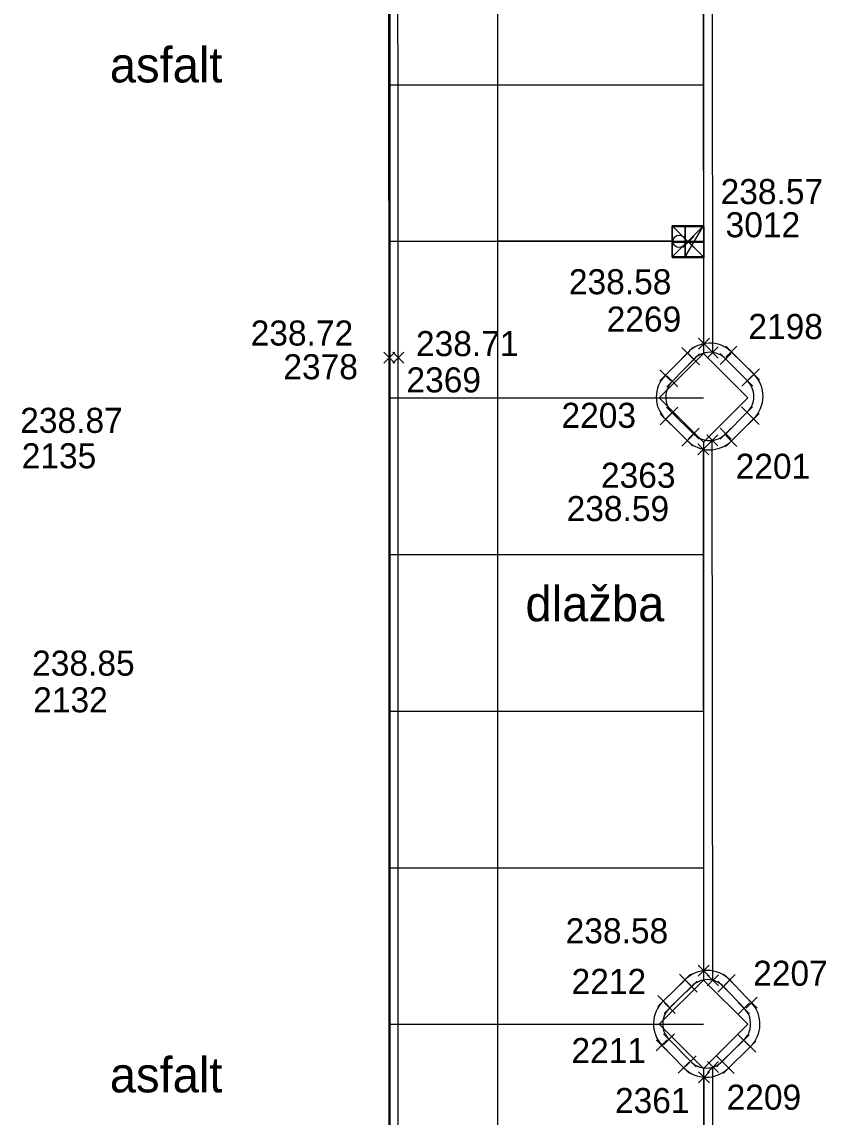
# Model space of a CAD drawing. Extents: x -264222 to -263676, y -1242344 to -1242060.
# Drawn here: x -264131.44 to -264118.61, y -1242231.96 to -1242214.48 of the extents above; entities that cross this region are included whole.
import ezdxf

# ---------------------------------------------------------------- set-up
doc = ezdxf.new("R2010")
doc.units = 0
for name, color, linetype in [('BODY_CISLO', 7, 'Continuous'), ('BODY_SYMBOL', 7, 'Continuous'), ('BODY_VYSKA', 7, 'Continuous'), ('BODY_VYSKY_UV', 7, 'Continuous'), ('KOORDINACNA_SITUACIA_DSP', 7, 'Continuous'), ('POPIS', 7, 'Continuous'), ('PROJEKT_DRS_OBRUBNIKY_KOMUNIKACIE', 7, 'Continuous'), ('PROJEKT_DRS_TDZ_VODOROVNE', 7, 'Continuous'), ('PROJEKT_DRS_UV_STAVBY', 7, 'Continuous'), ('SO_20-3_OBRUBNIKY_DOLNA_HRANA', 7, 'Continuous'), ('SO_20-3_OBRUBNIKY_HORNA_HRANA', 7, 'Continuous'), ('ULICNA_VPUST_POKLOP', 7, 'Continuous')]:
    doc.layers.add(name, color=color, linetype=linetype)

msp = doc.modelspace()

# ---------------------------------------------------------------- linework, layer by layer
at = {"layer": 'BODY_SYMBOL'}
for p, q in [((-264120.901, -1242218.083), (-264120.725, -1242217.907)), ((-264120.725, -1242218.083), (-264120.901, -1242217.907)), ((-264120.649, -1242219.705), (-264120.473, -1242219.529)), ((-264120.473, -1242219.705), (-264120.649, -1242219.529)), ((-264120.914, -1242219.853), (-264120.738, -1242219.677)), ((-264120.738, -1242219.853), (-264120.914, -1242219.677)), ((-264120.51, -1242219.845), (-264120.334, -1242219.669)), ((-264120.334, -1242219.845), (-264120.51, -1242219.669)), ((-264120.214, -1242219.833), (-264120.038, -1242219.657)), ((-264120.038, -1242219.833), (-264120.214, -1242219.657)), ((-264125.672, -1242219.928), (-264125.496, -1242219.752)), ((-264125.496, -1242219.928), (-264125.672, -1242219.752)), ((-264125.528, -1242219.929), (-264125.352, -1242219.753)), ((-264125.352, -1242219.929), (-264125.528, -1242219.753)), ((-264120.81, -1242219.952), (-264120.634, -1242219.776)), ((-264120.634, -1242219.952), (-264120.81, -1242219.776)), ((-264120.304, -1242219.948), (-264120.128, -1242219.772)), ((-264120.128, -1242219.948), (-264120.304, -1242219.772)), ((-264121.264, -1242220.207), (-264121.088, -1242220.031)), ((-264121.088, -1242220.207), (-264121.264, -1242220.031)), ((-264119.851, -1242220.193), (-264119.675, -1242220.017)), ((-264119.675, -1242220.193), (-264119.851, -1242220.017)), ((-264121.152, -1242220.303), (-264120.976, -1242220.127)), ((-264120.976, -1242220.303), (-264121.152, -1242220.127)), ((-264119.957, -1242220.297), (-264119.781, -1242220.121)), ((-264119.781, -1242220.297), (-264119.957, -1242220.121)), ((-264121.26, -1242220.911), (-264121.084, -1242220.735)), ((-264121.084, -1242220.911), (-264121.26, -1242220.735)), ((-264121.157, -1242220.806), (-264120.981, -1242220.63)), ((-264120.981, -1242220.806), (-264121.157, -1242220.63)), ((-264119.963, -1242220.801), (-264119.787, -1242220.625)), ((-264119.787, -1242220.801), (-264119.963, -1242220.625)), ((-264119.857, -1242220.905), (-264119.681, -1242220.729)), ((-264119.681, -1242220.905), (-264119.857, -1242220.729)), ((-264120.914, -1242221.253), (-264120.738, -1242221.077)), ((-264120.738, -1242221.253), (-264120.914, -1242221.077)), ((-264120.814, -1242221.143), (-264120.638, -1242220.967)), ((-264120.638, -1242221.143), (-264120.814, -1242220.967)), ((-264120.517, -1242221.248), (-264120.341, -1242221.072)), ((-264120.341, -1242221.248), (-264120.517, -1242221.072)), ((-264120.301, -1242221.142), (-264120.125, -1242220.966)), ((-264120.125, -1242221.142), (-264120.301, -1242220.966)), ((-264120.212, -1242221.257), (-264120.036, -1242221.081)), ((-264120.036, -1242221.257), (-264120.212, -1242221.081)), ((-264120.659, -1242221.389), (-264120.483, -1242221.213)), ((-264120.483, -1242221.389), (-264120.659, -1242221.213)), ((-264120.952, -1242229.86), (-264120.776, -1242229.684)), ((-264120.776, -1242229.86), (-264120.952, -1242229.684)), ((-264120.653, -1242229.713), (-264120.477, -1242229.537)), ((-264120.477, -1242229.713), (-264120.653, -1242229.537)), ((-264120.508, -1242229.867), (-264120.332, -1242229.691)), ((-264120.332, -1242229.867), (-264120.508, -1242229.691)), ((-264120.238, -1242229.862), (-264120.062, -1242229.686)), ((-264120.062, -1242229.862), (-264120.238, -1242229.686)), ((-264120.848, -1242229.967), (-264120.672, -1242229.791)), ((-264120.672, -1242229.967), (-264120.848, -1242229.791)), ((-264120.34, -1242229.967), (-264120.164, -1242229.791)), ((-264120.164, -1242229.967), (-264120.34, -1242229.791)), ((-264121.297, -1242230.198), (-264121.121, -1242230.022)), ((-264121.121, -1242230.198), (-264121.297, -1242230.022)), ((-264121.197, -1242230.308), (-264121.021, -1242230.132)), ((-264121.021, -1242230.308), (-264121.197, -1242230.132)), ((-264120.009, -1242230.313), (-264119.833, -1242230.137)), ((-264119.833, -1242230.313), (-264120.009, -1242230.137)), ((-264119.89, -1242230.227), (-264119.714, -1242230.051)), ((-264119.714, -1242230.227), (-264119.89, -1242230.051)), ((-264121.322, -1242230.905), (-264121.146, -1242230.729)), ((-264121.146, -1242230.905), (-264121.322, -1242230.729)), ((-264121.207, -1242230.811), (-264121.031, -1242230.635)), ((-264121.031, -1242230.811), (-264121.207, -1242230.635)), ((-264120.018, -1242230.826), (-264119.842, -1242230.65)), ((-264119.842, -1242230.826), (-264120.018, -1242230.65)), ((-264119.911, -1242230.929), (-264119.735, -1242230.753)), ((-264119.735, -1242230.929), (-264119.911, -1242230.753)), ((-264120.971, -1242231.265), (-264120.795, -1242231.089)), ((-264120.795, -1242231.265), (-264120.971, -1242231.089)), ((-264120.864, -1242231.161), (-264120.688, -1242230.985)), ((-264120.688, -1242231.161), (-264120.864, -1242230.985)), ((-264120.506, -1242231.253), (-264120.33, -1242231.077)), ((-264120.33, -1242231.253), (-264120.506, -1242231.077)), ((-264120.36, -1242231.163), (-264120.184, -1242230.987)), ((-264120.184, -1242231.163), (-264120.36, -1242230.987)), ((-264120.257, -1242231.27), (-264120.081, -1242231.094)), ((-264120.081, -1242231.27), (-264120.257, -1242231.094)), ((-264120.648, -1242231.415), (-264120.472, -1242231.239)), ((-264120.472, -1242231.415), (-264120.648, -1242231.239))]:
    msp.add_line(p, q, dxfattribs=at)
at = {"layer": 'KOORDINACNA_SITUACIA_DSP'}
for p, q in [((-264123.854, -1242207), (-264123.854, -1242236.976)), ((-264120.568, -1242211.189), (-264120.568, -1242219.774)), ((-264120.86, -1242218.232), (-264120.86, -1242217.732)), ((-264120.86, -1242217.732), (-264120.57, -1242217.732)), ((-264120.86, -1242218.232), (-264120.57, -1242217.732)), ((-264120.86, -1242218.232), (-264120.57, -1242217.732)), ((-264120.57, -1242217.732), (-264120.86, -1242217.732)), ((-264120.86, -1242217.732), (-264120.86, -1242218.232)), ((-264120.57, -1242217.732), (-264120.57, -1242218.232)), ((-264121.058, -1242217.982), (-264123.854, -1242217.982)), ((-264120.57, -1242218.232), (-264120.86, -1242218.232)), ((-264120.568, -1242221.189), (-264120.568, -1242229.774)), ((-264120.568, -1242231.189), (-264120.568, -1242239.774))]:
    msp.add_line(p, q, dxfattribs=at)
for points in [[(-264120.568, -1242219.775), (-264119.861, -1242220.482), (-264120.568, -1242221.189), (-264121.275, -1242220.482)], [(-264120.568, -1242229.775), (-264119.861, -1242230.482), (-264120.568, -1242231.189), (-264121.275, -1242230.482)]]:
    msp.add_lwpolyline(points, close=True, dxfattribs=at)
msp.add_circle((-264120.958, -1242217.982), 0.1, dxfattribs=at)
at = {"layer": 'PROJEKT_DRS_OBRUBNIKY_KOMUNIKACIE'}
for p, q in [((-264125.568, -1242270.982), (-264125.568, -1242191.482)), ((-264120.568, -1242211.189), (-264120.568, -1242219.774)), ((-264120.568, -1242221.189), (-264120.568, -1242229.774)), ((-264120.568, -1242231.189), (-264120.568, -1242239.774))]:
    msp.add_line(p, q, dxfattribs=at)
for points in [[(-264120.568, -1242219.775), (-264119.861, -1242220.482), (-264120.568, -1242221.189), (-264121.275, -1242220.482), (-264120.568, -1242219.775)], [(-264120.568, -1242229.775), (-264119.861, -1242230.482), (-264120.568, -1242231.189), (-264121.275, -1242230.482), (-264120.568, -1242229.775)]]:
    msp.add_lwpolyline(points, dxfattribs=at)
at = {"layer": 'PROJEKT_DRS_TDZ_VODOROVNE'}
for p, q in [((-264125.568, -1242215.482), (-264120.568, -1242215.482)), ((-264125.568, -1242217.982), (-264120.568, -1242217.982)), ((-264125.568, -1242220.482), (-264120.568, -1242220.482)), ((-264125.568, -1242222.982), (-264120.568, -1242222.982)), ((-264125.568, -1242225.482), (-264120.568, -1242225.482)), ((-264125.568, -1242227.982), (-264120.568, -1242227.982)), ((-264125.568, -1242230.482), (-264120.568, -1242230.482))]:
    msp.add_line(p, q, dxfattribs=at)
at = {"layer": 'PROJEKT_DRS_UV_STAVBY'}
msp.add_lwpolyline([(-264121.07, -1242218.232), (-264121.07, -1242217.732), (-264120.57, -1242217.732), (-264120.57, -1242218.232), (-264121.07, -1242218.232), (-264120.57, -1242217.732), (-264121.07, -1242217.732), (-264120.57, -1242218.232)], dxfattribs=at)
at = {"layer": 'SO_20-3_OBRUBNIKY_DOLNA_HRANA'}
for p, q in [((-264120.561, -1242219.617), (-264120.573, -1242211.348)), ((-264120.826, -1242219.765), (-264121.176, -1242220.119)), ((-264120.126, -1242219.745), (-264119.763, -1242220.105)), ((-264120.826, -1242221.165), (-264121.172, -1242220.823)), ((-264119.769, -1242220.817), (-264120.124, -1242221.169)), ((-264120.565, -1242229.625), (-264120.571, -1242221.301)), ((-264121.209, -1242230.11), (-264120.864, -1242229.772)), ((-264120.15, -1242229.774), (-264119.802, -1242230.139)), ((-264120.883, -1242231.177), (-264121.234, -1242230.817)), ((-264119.823, -1242230.841), (-264120.169, -1242231.182)), ((-264120.554, -1242239.646), (-264120.56, -1242231.327))]:
    msp.add_line(p, q, dxfattribs=at)
for points in [[(-264125.573, -1242270.915), (-264125.578, -1242264.895), (-264125.575, -1242255.299), (-264125.581, -1242244.324), (-264125.582, -1242233.844), (-264125.584, -1242219.84), (-264125.593, -1242209.81), (-264125.59, -1242197.798), (-264125.59, -1242191.484)], [(-264125.429, -1242270.662), (-264125.437, -1242264.9), (-264125.431, -1242255.315), (-264125.435, -1242244.34), (-264125.439, -1242233.845), (-264125.44, -1242219.841), (-264125.448, -1242209.814), (-264125.447, -1242197.797), (-264125.435, -1242191.484)]]:
    msp.add_lwpolyline(points, dxfattribs=at)
for centre, major_axis, ratio, start_param, end_param in [((-264120.466, -1242220.098), (-0.488, 0.046), 0.999933, 4.040271, 5.631388), ((-264120.832, -1242220.469), (0.216, -0.441), 0.999979, 3.462744, 5.062042), ((-264120.123, -1242220.458), (0.183, 0.47), 0.998877, 4.292351, 5.859751), ((-264120.473, -1242220.812), (0.444, 0.228), 0.999924, 3.453691, 5.012696), ((-264120.508, -1242230.12), (-0.447, -0.218), 0.99998, 3.456563, 5.056606), ((-264120.863, -1242230.476), (0.378, -0.333), 0.999798, 3.050143, 4.60564), ((-264120.165, -1242230.48), (0.194, 0.458), 0.999375, 4.300208, 5.866467), ((-264120.524, -1242230.826), (0.502, -0.004), 0.999977, 3.921399, 5.503379)]:
    msp.add_ellipse(centre, major_axis=major_axis, ratio=ratio, start_param=start_param, end_param=end_param, dxfattribs=at)
at = {"layer": 'SO_20-3_OBRUBNIKY_HORNA_HRANA'}
for p, q in [((-264120.422, -1242219.757), (-264120.426, -1242211.199)), ((-264121.064, -1242220.215), (-264120.722, -1242219.864)), ((-264120.216, -1242219.86), (-264119.869, -1242220.209)), ((-264120.726, -1242221.055), (-264121.069, -1242220.718)), ((-264119.875, -1242220.713), (-264120.213, -1242221.054)), ((-264120.42, -1242229.779), (-264120.429, -1242221.16)), ((-264121.109, -1242230.22), (-264120.76, -1242229.879)), ((-264120.252, -1242229.879), (-264119.921, -1242230.225)), ((-264120.776, -1242231.073), (-264121.119, -1242230.723)), ((-264119.93, -1242230.738), (-264120.272, -1242231.075)), ((-264120.414, -1242239.803), (-264120.418, -1242231.165))]:
    msp.add_line(p, q, dxfattribs=at)
for centre, major_axis, ratio, start_param, end_param in [((-264120.467, -1242220.104), (-0.348, -0.038), 0.999249, 3.8025, 5.417886), ((-264120.818, -1242220.469), (-0.004, -0.354), 0.998351, 3.922572, 5.502206), ((-264120.115, -1242220.458), (0.08, 0.341), 0.999323, 4.126273, 5.733445), ((-264120.47, -1242220.803), (0.356, 0.05), 0.998417, 3.778494, 5.368139), ((-264120.506, -1242230.114), (-0.342, -0.05), 0.999153, 3.74362, 5.393103), ((-264120.865, -1242230.477), (0.068, -0.348), 0.997854, 3.70915, 5.287368), ((-264120.171, -1242230.477), (0.16, 0.317), 0.998795, 4.356433, 5.972219), ((-264120.523, -1242230.834), (0.348, -0.001), 0.998886, 3.904066, 5.520712)]:
    msp.add_ellipse(centre, major_axis=major_axis, ratio=ratio, start_param=start_param, end_param=end_param, dxfattribs=at)
at = {"layer": 'ULICNA_VPUST_POKLOP'}
msp.add_line((-264120.813, -1242217.995), (-264120.813, -1242217.995), dxfattribs=at)
msp.add_lwpolyline([(-264121.063, -1242217.995), (-264121.063, -1242217.745), (-264120.563, -1242217.745), (-264120.563, -1242218.245), (-264121.063, -1242218.245), (-264121.063, -1242217.995), (-264120.563, -1242217.995)], dxfattribs=at)

# ---------------------------------------------------------------- texts
at = {"layer": 'BODY_CISLO'}
for s, p in [('3012', (-264120.216, -1242217.917)), ('2269', (-264122.114, -1242219.423)), ('2198', (-264119.853, -1242219.541)), ('2378', (-264127.273, -1242220.184)), ('2369', (-264125.309, -1242220.394)), ('2203', (-264122.835, -1242220.96)), ('2135', (-264131.448, -1242221.606)), ('2201', (-264120.056, -1242221.773)), ('2363', (-264122.205, -1242221.917)), ('2132', (-264131.265, -1242225.502)), ('2207', (-264119.776, -1242229.867)), ('2212', (-264122.674, -1242229.997)), ('2211', (-264122.676, -1242231.101)), ('2209', (-264120.2, -1242231.846)), ('2361', (-264121.981, -1242231.899))]:
    msp.add_text(s, height=0.4, dxfattribs=at).set_placement(p)
at = {"layer": 'BODY_VYSKA'}
for s, p in [('238.58', (-264122.717, -1242218.827)), ('238.72', (-264127.795, -1242219.646)), ('238.71', (-264125.157, -1242219.815)), ('238.87', (-264131.472, -1242221.04)), ('238.59', (-264122.753, -1242222.449)), ('238.85', (-264131.282, -1242224.916)), ('238.58', (-264122.768, -1242229.189))]:
    msp.add_text(s, height=0.4, dxfattribs=at).set_placement(p)
at = {"layer": 'BODY_VYSKY_UV'}
msp.add_text('238.57', height=0.4, dxfattribs=at).set_placement((-264120.296, -1242217.388))
at = {"layer": 'POPIS'}
for p in [(-264130.042, -1242215.445), (-264130.042, -1242231.569)]:
    msp.add_text('asfalt', height=0.5625, dxfattribs=at).set_placement(p)
msp.add_text('dlažba', height=0.5625, rotation=360, dxfattribs=at).set_placement((-264123.41, -1242224.048))

doc.saveas('drawing.dxf')
